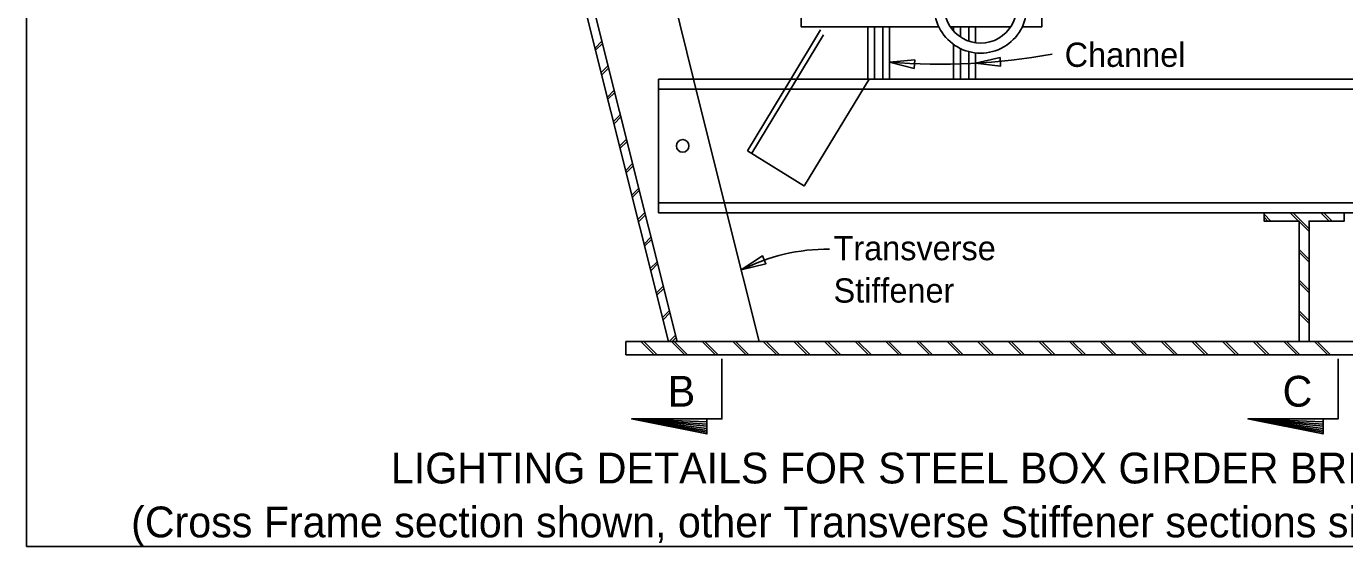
# Model space of a CAD drawing. Extents: x 112544 to 112597.1, y 111084 to 111107.1.
# Drawn here: x 112543.99 to 112552.21, y 111085.9 to 111089.14 of the extents above; entities that cross this region are included whole.
import ezdxf

# ---------------------------------------------------------------- set-up
doc = ezdxf.new("R2010")
doc.units = 0
for name, color, linetype in [('ActivePts-ConstElements', 7, 'Continuous'), ('Dimension', 7, 'Continuous'), ('Lighting', 7, 'Continuous'), ('Miscellaneous', 7, 'Continuous'), ('SteelGirder', 7, 'Continuous'), ('SteelGirder_h', 7, 'Continuous'), ('TextStructures', 7, 'Continuous')]:
    doc.layers.add(name, color=color, linetype=linetype)

msp = doc.modelspace()

# ---------------------------------------------------------------- linework, layer by layer
at = {"layer": 'ActivePts-ConstElements'}
msp.add_lwpolyline([(112543.9918, 111085.9039), (112574.7797, 111085.9039), (112574.7797, 111105.3634), (112543.9918, 111105.3634)], close=True, dxfattribs=at)
at = {"layer": 'Dimension'}
for p, q in [((112548.2352, 111086.6808), (112547.7664, 111086.6983)), ((112547.7664, 111086.6983), (112548.2352, 111086.6658)), ((112548.2352, 111086.652), (112547.7664, 111086.6983)), ((112547.7664, 111086.6983), (112548.2352, 111086.6383)), ((112548.2352, 111086.6258), (112547.7664, 111086.6983)), ((112547.7664, 111086.6983), (112548.2352, 111086.6158)), ((112552.0777, 111086.6808), (112551.6089, 111086.6983)), ((112551.6089, 111086.6983), (112552.0777, 111086.6658)), ((112552.0777, 111086.652), (112551.6089, 111086.6983)), ((112551.6089, 111086.6983), (112552.0777, 111086.6383)), ((112552.0777, 111086.6258), (112551.6089, 111086.6983)), ((112551.6089, 111086.6983), (112552.0777, 111086.6158))]:
    msp.add_line(p, q, dxfattribs=at)
for points in [[(112549.374, 111088.921), (112549.5277, 111088.8826), (112549.5317, 111088.9354)], [(112549.9097, 111088.9154), (112550.0672, 111088.8977), (112550.0642, 111088.9505)], [(112548.4499, 111087.6267), (112548.6036, 111087.6651), (112548.5824, 111087.7136)]]:
    msp.add_lwpolyline(points, close=True, dxfattribs=at)
for points in [[(112548.3289, 111087.0733), (112548.329, 111086.6983), (112547.7664, 111086.6983), (112548.2352, 111086.6045), (112548.2352, 111086.6983)], [(112552.1714, 111087.0733), (112552.1715, 111086.6983), (112551.6089, 111086.6983), (112552.0777, 111086.6045), (112552.0777, 111086.6983)]]:
    msp.add_lwpolyline(points, dxfattribs=at)
msp.add_arc((112549.6842, 111092.9544), 4.0453, 265.60117, 280.01859, dxfattribs=at)
msp.add_ellipse((112548.9925, 111086.4439), major_axis=(-0.0084, -1.3128), ratio=0.953713, start_param=3.141601, end_param=3.59647, dxfattribs=at)
at = {"layer": 'Lighting'}
for p, q in [((112549.2386, 111089.1409), (112549.2386, 111088.8165)), ((112549.2802, 111089.1409), (112549.2802, 111088.8165)), ((112549.3324, 111089.1409), (112549.3324, 111088.8165)), ((112549.374, 111089.1409), (112549.374, 111088.8165)), ((112549.7744, 111089.1409), (112549.7744, 111089.1151)), ((112549.816, 111089.1409), (112549.816, 111089.0789)), ((112549.8682, 111089.1409), (112549.8682, 111089.0528)), ((112549.9098, 111089.1409), (112549.9098, 111089.0426)), ((112549.7744, 111089.0317), (112549.7744, 111088.8165)), ((112549.816, 111089.0069), (112549.816, 111088.8165)), ((112549.8682, 111088.9874), (112549.8682, 111088.8165)), ((112549.9098, 111088.9796), (112549.9098, 111088.8165))]:
    msp.add_line(p, q, dxfattribs=at)
for radius, start, end in [(0.2882, 179.99549, 0.00006), (0.2257, 180, 0.00003)]:
    msp.add_arc((112549.9422, 111089.2659), radius, start, end, dxfattribs=at)
at = {"layer": 'Miscellaneous'}
for p, q in [((112547.5383, 111089.0098), (112547.5813, 111089.0528)), ((112547.5419, 111088.9957), (112547.5848, 111089.0387)), ((112547.5765, 111088.8571), (112547.6195, 111088.9001)), ((112547.58, 111088.843), (112547.623, 111088.8859)), ((112547.6147, 111088.7044), (112547.6577, 111088.7473)), ((112547.6182, 111088.6902), (112547.6612, 111088.7332)), ((112547.6529, 111088.5516), (112547.6958, 111088.5946)), ((112547.6564, 111088.5375), (112547.6994, 111088.5805)), ((112547.6911, 111088.3989), (112547.734, 111088.4419)), ((112547.6946, 111088.3848), (112547.7376, 111088.4277)), ((112547.7292, 111088.2462), (112547.7722, 111088.2891)), ((112547.7328, 111088.232), (112547.7757, 111088.275)), ((112547.7674, 111088.0934), (112547.8104, 111088.1364)), ((112547.771, 111088.0793), (112547.8139, 111088.1223)), ((112547.8056, 111087.9407), (112547.8486, 111087.9837)), ((112547.8092, 111087.9266), (112547.8521, 111087.9695)), ((112551.7522, 111087.9311), (112551.7098, 111087.9735)), ((112551.7346, 111087.9311), (112551.7098, 111087.9558)), ((112551.9255, 111087.9311), (112551.8733, 111087.9832)), ((112551.9911, 111087.8831), (112551.891, 111087.9832)), ((112551.9911, 111087.8654), (112551.9287, 111087.9279)), ((112552.1164, 111087.9311), (112552.0643, 111087.9832)), ((112552.1341, 111087.9311), (112552.0819, 111087.9832)), ((112547.8438, 111087.788), (112547.8868, 111087.8309)), ((112547.8473, 111087.7738), (112547.8903, 111087.8168)), ((112551.9911, 111087.6922), (112551.9287, 111087.7546)), ((112547.882, 111087.6352), (112547.9249, 111087.6782)), ((112547.8855, 111087.6211), (112547.9285, 111087.6641)), ((112551.9911, 111087.6745), (112551.9287, 111087.737)), ((112547.9202, 111087.4825), (112547.9631, 111087.5255)), ((112547.9237, 111087.4684), (112547.9667, 111087.5113)), ((112551.9911, 111087.5013), (112551.9287, 111087.5637)), ((112551.9911, 111087.4836), (112551.9287, 111087.546)), ((112547.9584, 111087.3298), (112548.0013, 111087.3727)), ((112547.9619, 111087.3156), (112548.0048, 111087.3586)), ((112551.9911, 111087.3103), (112551.9287, 111087.3728)), ((112551.9911, 111087.2927), (112551.9287, 111087.3551)), ((112547.907, 111087.0979), (112547.8237, 111087.1812)), ((112547.9247, 111087.0979), (112547.8414, 111087.1812)), ((112548.0007, 111087.1812), (112548.0395, 111087.22)), ((112548.0979, 111087.0979), (112548.0147, 111087.1812)), ((112548.0184, 111087.1812), (112548.043, 111087.2058)), ((112548.1156, 111087.0979), (112548.0323, 111087.1812)), ((112548.2889, 111087.0979), (112548.2056, 111087.1812)), ((112548.3065, 111087.0979), (112548.2233, 111087.1812)), ((112548.4798, 111087.0979), (112548.3965, 111087.1812)), ((112548.4975, 111087.0979), (112548.4142, 111087.1812)), ((112548.6707, 111087.0979), (112548.5874, 111087.1812)), ((112548.6884, 111087.0979), (112548.6051, 111087.1812)), ((112548.8616, 111087.0979), (112548.7783, 111087.1812)), ((112548.8793, 111087.0979), (112548.796, 111087.1812)), ((112549.0525, 111087.0979), (112548.9692, 111087.1812)), ((112549.0702, 111087.0979), (112548.9869, 111087.1812)), ((112549.2434, 111087.0979), (112549.1602, 111087.1812)), ((112549.2611, 111087.0979), (112549.1778, 111087.1812)), ((112549.4344, 111087.0979), (112549.3511, 111087.1812)), ((112549.452, 111087.0979), (112549.3688, 111087.1812)), ((112549.6253, 111087.0979), (112549.542, 111087.1812)), ((112549.643, 111087.0979), (112549.5597, 111087.1812)), ((112549.8162, 111087.0979), (112549.7329, 111087.1812)), ((112549.8339, 111087.0979), (112549.7506, 111087.1812)), ((112550.0071, 111087.0979), (112549.9238, 111087.1812)), ((112550.0248, 111087.0979), (112549.9415, 111087.1812)), ((112550.198, 111087.0979), (112550.1148, 111087.1812)), ((112550.2157, 111087.0979), (112550.1324, 111087.1812)), ((112550.389, 111087.0979), (112550.3057, 111087.1812)), ((112550.4066, 111087.0979), (112550.3234, 111087.1812)), ((112550.5799, 111087.0979), (112550.4966, 111087.1812)), ((112550.5976, 111087.0979), (112550.5143, 111087.1812)), ((112550.7708, 111087.0979), (112550.6875, 111087.1812)), ((112550.7885, 111087.0979), (112550.7052, 111087.1812)), ((112550.9617, 111087.0979), (112550.8784, 111087.1812)), ((112550.9794, 111087.0979), (112550.8961, 111087.1812)), ((112551.1526, 111087.0979), (112551.0694, 111087.1812)), ((112551.1703, 111087.0979), (112551.087, 111087.1812)), ((112551.3436, 111087.0979), (112551.2603, 111087.1812)), ((112551.3612, 111087.0979), (112551.278, 111087.1812)), ((112551.5345, 111087.0979), (112551.4512, 111087.1812)), ((112551.5522, 111087.0979), (112551.4689, 111087.1812)), ((112551.7254, 111087.0979), (112551.6421, 111087.1812)), ((112551.7431, 111087.0979), (112551.6598, 111087.1812)), ((112551.9163, 111087.0979), (112551.833, 111087.1812)), ((112551.934, 111087.0979), (112551.8507, 111087.1812)), ((112551.9295, 111087.1811), (112551.9287, 111087.1819)), ((112552.1072, 111087.0979), (112552.0239, 111087.1812)), ((112552.1249, 111087.0979), (112552.0416, 111087.1812)), ((112547.7338, 111087.0979), (112547.7292, 111087.1026))]:
    msp.add_line(p, q, dxfattribs=at)
at = {"layer": 'SteelGirder'}
for p, q in [((112546.433, 111093.4311), (112547.9955, 111087.1812)), ((112546.4867, 111093.4311), (112548.0492, 111087.1812)), ((112547.1656, 111092.7644), (112548.1528, 111088.8165)), ((112548.7595, 111088.8165), (112548.9444, 111089.1222)), ((112547.9346, 111087.9832), (112547.9346, 111088.8165)), ((112547.9346, 111088.8164), (112552.7436, 111088.8164)), ((112547.9346, 111088.754), (112552.7436, 111088.754)), ((112547.9346, 111088.0457), (112552.7436, 111088.0457)), ((112547.9346, 111087.9832), (112552.7436, 111087.9832)), ((112548.3608, 111087.9832), (112548.5614, 111087.1812)), ((112548.4598, 111087.1812), (112547.7292, 111087.1812)), ((112547.7292, 111087.1812), (112547.7292, 111087.0979)), ((112547.7292, 111087.1812), (112547.7292, 111087.0979)), ((112551.9601, 111087.1812), (112548.46, 111087.1812)), ((112552.7436, 111087.1812), (112551.96, 111087.1812)), ((112552.7436, 111087.0979), (112547.7292, 111087.0979))]:
    msp.add_line(p, q, dxfattribs=at)
for points in [[(112550.2018, 111089.1409), (112550.3242, 111089.1409), (112550.3242, 111092.3909), (112549.4361, 111092.3909)], [(112548.8242, 111091.2491), (112548.8242, 111089.1409), (112549.6826, 111089.1409)], [(112549.7543, 111089.1409), (112550.13, 111089.1409)]]:
    msp.add_lwpolyline(points, dxfattribs=at)
msp.add_lwpolyline([(112551.9287, 111087.1811), (112551.9287, 111087.9311), (112551.7098, 111087.9311), (112551.7098, 111087.9832), (112552.2099, 111087.9832), (112552.2099, 111087.9311), (112551.9911, 111087.9311), (112551.9911, 111087.1811)], close=True, dxfattribs=at)
msp.add_circle((112548.0848, 111088.3998), 0.0391, dxfattribs=at)
at = {"layer": 'SteelGirder_h'}
for p, q in [((112548.5159, 111088.3535), (112548.963, 111089.0926)), ((112548.1525, 111088.8165), (112548.3608, 111087.9832)), ((112548.4894, 111088.3699), (112548.7595, 111088.8165)), ((112548.8447, 111088.152), (112549.2467, 111088.8165)), ((112548.4894, 111088.3699), (112548.8433, 111088.1498))]:
    msp.add_line(p, q, dxfattribs=at)

# ---------------------------------------------------------------- texts
at = {"layer": 'Dimension'}
for s, height, p in [('Transverse', 0.1512, (112549.0256, 111087.6871)), ('Stiffener', 0.1512, (112549.0256, 111087.4231)), ('LIGHTING DETAILS FOR STEEL BOX GIRDER BRIDGE', 0.192, (112546.265, 111086.296)), ('(Cross Frame section shown, other Transverse Stiffener sections similar)', 0.192, (112544.6451, 111085.96))]:
    msp.add_text(s, height=height, dxfattribs=at).set_placement(p)
at = {"layer": 'TextStructures'}
for s, height, p in [('Channel', 0.1512, (112550.4666, 111088.8923)), ('B', 0.192, (112547.9915, 111086.7746)), ('C', 0.192, (112551.8257, 111086.7746))]:
    msp.add_text(s, height=height, dxfattribs=at).set_placement(p)

doc.saveas('drawing.dxf')
